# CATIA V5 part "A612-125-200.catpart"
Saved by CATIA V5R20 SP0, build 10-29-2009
Part number: A612-125-200
Source: Unknown
Property "A": "30.000"
Property "ARTICLENO": "A612-125-200"
Property "B": "50.000"
Property "BOMINFO": "A612-125-200"
Property "CODE": "A612-125-200"
Property "D": "22.000"
Property "FORM": "A"
Property "L": "200.000"
Property "L1": "45.000"
Property "L2": "110.000"
Property "L3": "0.000"
Property "LINA": "A612-125-200"
Property "NB": "A612-125-200"
Property "NBSYN": "$CODE."
Property "NN": "A612"
Property "NT": "CDI 3357 E-Type Wear Plates, steel and self-lubricating"
Property "SUPPLIER": "CF"
Property "T": "30.000"
Property "W": "125.000"
Bounding box of the stored display mesh (mm): x 0 to 30, y 0 to 200, z 0 to 125
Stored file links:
  C:\Users\Utente\Desktop\3D files A612\A612-125-200.catpart
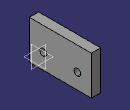
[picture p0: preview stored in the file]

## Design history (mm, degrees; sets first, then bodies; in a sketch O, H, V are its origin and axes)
Body1 "Geometry.1" (main body)
  Solid1 "A612-125-200.catpart": solid without history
